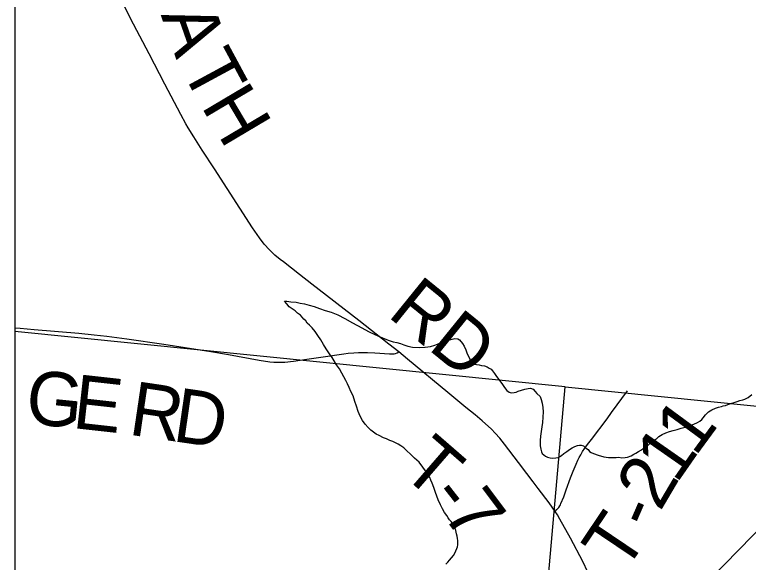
# Model space of a CAD drawing. Extents: x 0 to 34, y 0 to 22.
# Drawn here: x 22.516 to 23.289, y 17.774 to 18.35 of the extents above; entities that cross this region are included whole.
import ezdxf

# ---------------------------------------------------------------- set-up
doc = ezdxf.new("R2010")
doc.units = 0
for name, color, linetype in [('GM_X_County_Road', 7, 'Continuous'), ('GM_X_Minor_River', 7, 'Continuous'), ('GM_X_Section', 7, 'Continuous'), ('GM_X_State_Route', 7, 'Continuous'), ('GM_X_Township_Road', 7, 'Continuous'), ('GM_X_Township_Road_Text', 7, 'Continuous'), ('SH_Border', 7, 'Continuous'), ('SH_Data', 7, 'Continuous')]:
    doc.layers.add(name, color=color, linetype=linetype)

msp = doc.modelspace()

# ---------------------------------------------------------------- linework, layer by layer
at = {"layer": 'GM_X_County_Road'}
msp.add_lwpolyline([(22.51637, 18.01675), (22.51637, 17.0024), (23.00697, 16.95129), (23.09601, 17.95858)], close=True, dxfattribs=at)
at = {"layer": 'GM_X_Minor_River'}
for points in [[(22.97037, 17.77207), (22.9723, 17.77432), (22.97423, 17.77656), (22.97617, 17.77881), (22.97849, 17.78144), (22.97966, 17.7837), (22.98084, 17.78634), (22.98202, 17.7886), (22.98243, 17.7905), (22.98284, 17.79239), (22.98287, 17.79467), (22.98291, 17.79695), (22.98257, 17.79924), (22.98222, 17.80152), (22.98151, 17.8042), (22.9808, 17.80763), (22.97971, 17.81069), (22.97823, 17.813), (22.97713, 17.81529), (22.97602, 17.81721), (22.97415, 17.81876), (22.97267, 17.82107), (22.97118, 17.82337), (22.96895, 17.82645), (22.96674, 17.83029), (22.96453, 17.83451), (22.96234, 17.83987), (22.95942, 17.84752), (22.95761, 17.85287), (22.95578, 17.85746), (22.95431, 17.86053), (22.9536, 17.8632), (22.95249, 17.86512), (22.951, 17.86704), (22.94989, 17.86896), (22.94209, 17.87936), (22.93722, 17.88362), (22.93311, 17.88787), (22.92937, 17.89135), (22.926, 17.89445), (22.923, 17.89678), (22.91999, 17.89835), (22.91736, 17.89991), (22.91434, 17.9011), (22.91132, 17.90229), (22.90793, 17.90387), (22.90453, 17.90507), (22.90002, 17.90742), (22.897, 17.90899), (22.894, 17.91094), (22.89138, 17.91327), (22.88838, 17.91598), (22.8854, 17.91945), (22.88243, 17.9233), (22.88022, 17.9279), (22.87802, 17.93287), (22.87621, 17.93823), (22.87439, 17.9432), (22.87259, 17.94931), (22.87039, 17.95391), (22.86855, 17.95812), (22.86672, 17.96195), (22.86487, 17.9654), (22.86304, 17.96924), (22.86082, 17.97307), (22.85824, 17.97767), (22.85527, 17.98191), (22.85268, 17.98613), (22.85046, 17.98959), (22.84786, 17.99343), (22.84415, 17.99882), (22.84156, 18.00342), (22.8386, 18.00803), (22.83564, 18.01264), (22.83267, 18.01687), (22.82969, 18.02072), (22.8267, 18.02343), (22.82446, 18.02575), (22.82297, 18.02805), (22.82073, 18.02999), (22.81738, 18.03423), (22.81399, 18.03619), (22.81175, 18.0385), (22.8095, 18.04006), (22.80537, 18.04279), (22.80276, 18.04587), (22.80053, 18.04895), (22.80281, 18.04891)], [(22.80281, 18.04891), (22.80697, 18.04809), (22.81266, 18.04761), (22.81682, 18.04678), (22.82136, 18.04595), (22.82628, 18.04472), (22.83157, 18.04312), (22.83723, 18.04112), (22.84327, 18.03912), (22.84969, 18.03712), (22.85648, 18.03434), (22.86401, 18.03042), (22.87191, 18.0261), (22.8817, 18.02062), (22.88885, 18.01708), (22.89564, 18.01393), (22.90129, 18.01118), (22.90619, 18.0092), (22.91072, 18.0076), (22.91487, 18.00601), (22.91865, 18.00519), (22.92244, 18.00436), (22.92621, 18.00278), (22.93036, 18.00157), (22.93528, 18.00035), (22.94287, 18.00023), (22.94857, 18.00051), (22.95428, 18.00118), (22.95885, 18.00262), (22.96229, 18.00409), (22.96535, 18.00556), (22.96879, 18.00664), (22.97184, 18.00773), (22.97412, 18.00807), (22.97984, 18.0095), (22.98287, 18.00907), (22.98476, 18.00828), (22.98773, 18.00442), (22.98958, 18.00135), (22.99142, 17.99752), (22.99287, 17.99332), (22.99471, 17.98949), (22.99617, 17.98604), (22.99803, 17.98373), (23.00067, 17.98254), (23.00256, 17.98213), (23.00521, 17.98171), (23.00786, 17.98129), (23.01089, 17.98085), (23.01391, 17.97967), (23.01579, 17.97849), (23.01805, 17.97732), (23.01954, 17.97539), (23.02139, 17.9727), (23.02362, 17.96962), (23.02697, 17.965), (23.02994, 17.96116), (23.03217, 17.95808), (23.0344, 17.955), (23.03702, 17.95306), (23.03891, 17.95226), (23.04233, 17.95259), (23.04423, 17.95294), (23.04653, 17.95404), (23.04996, 17.95512), (23.0534, 17.95621), (23.05683, 17.95691), (23.05949, 17.95725), (23.06213, 17.95644), (23.06437, 17.95374), (23.06624, 17.95181), (23.0696, 17.94872), (23.07069, 17.94528), (23.07176, 17.94146), (23.07245, 17.93688), (23.07276, 17.93232), (23.0722, 17.9213), (23.07137, 17.91676), (23.07053, 17.91183), (23.07008, 17.90689), (23.06962, 17.90234), (23.06953, 17.89664), (23.07024, 17.89321), (23.07095, 17.89053), (23.07168, 17.88862), (23.07506, 17.8859), (23.07732, 17.88473), (23.07996, 17.88392), (23.083, 17.88387), (23.08604, 17.8842), (23.0887, 17.88454), (23.09215, 17.88638), (23.09446, 17.88862), (23.09753, 17.89085), (23.1006, 17.89271), (23.10329, 17.89456), (23.10597, 17.89604), (23.10902, 17.89713), (23.11093, 17.89747), (23.11282, 17.89744), (23.11509, 17.89665)], [(23.11509, 17.89665), (23.11733, 17.89471), (23.11996, 17.89277), (23.12145, 17.89084), (23.12333, 17.88967), (23.12559, 17.88849), (23.1305, 17.88689), (23.13654, 17.88527), (23.14147, 17.88443), (23.14412, 17.88438), (23.1464, 17.88435), (23.14944, 17.8843), (23.15248, 17.88462), (23.15551, 17.8842), (23.15893, 17.88452), (23.16159, 17.88486), (23.16541, 17.88631), (23.16809, 17.88779), (23.17039, 17.88889), (23.17308, 17.89075), (23.17614, 17.8926), (23.1796, 17.8952), (23.18304, 17.89704), (23.18574, 17.89966), (23.18882, 17.90227), (23.19189, 17.90412), (23.19458, 17.90636), (23.19803, 17.90858), (23.20186, 17.91042), (23.20568, 17.91188), (23.20949, 17.91295), (23.21368, 17.91402), (23.21788, 17.9151), (23.22359, 17.91652), (23.22741, 17.91798), (23.23123, 17.91944), (23.23506, 17.92127), (23.23774, 17.92275), (23.23966, 17.92424), (23.24121, 17.92611), (23.24354, 17.92912), (23.24663, 17.93249), (23.25046, 17.9347), (23.25428, 17.93616), (23.25733, 17.93725), (23.26038, 17.93796), (23.26229, 17.93869), (23.26457, 17.93903), (23.26725, 17.94013), (23.27679, 17.94339), (23.27984, 17.94448), (23.28289, 17.94519), (23.28518, 17.94591), (23.28862, 17.94738), (23.29247, 17.95073)]]:
    msp.add_lwpolyline(points, dxfattribs=at)
at = {"layer": 'GM_X_Section'}
msp.add_lwpolyline([(24.0891, 17.85881), (23.98418, 16.85292), (23.00697, 16.95129), (23.09601, 17.95858)], close=True, dxfattribs=at)
at = {"layer": 'GM_X_State_Route'}
msp.add_lwpolyline([(23.24886, 17.75663), (23.3079, 17.8171)], dxfattribs=at)
at = {"layer": 'GM_X_Township_Road'}
for points in [[(22.79922, 18.09016), (22.79599, 18.09269), (22.79041, 18.09729), (22.78447, 18.1028), (22.77898, 18.10883), (22.77403, 18.11531), (22.7667, 18.12604), (22.72669, 18.18796), (22.71371, 18.20778), (22.70496, 18.22167), (22.6991, 18.23095), (22.6966, 18.23521), (22.6912, 18.245), (22.67457, 18.27696), (22.65786, 18.30886), (22.63825, 18.34628), (22.62637, 18.37056)], [(22.92071, 17.99537), (22.91028, 18.00373), (22.87873, 18.02843), (22.82934, 18.06673), (22.81618, 18.07692), (22.79922, 18.09016)], [(22.51637, 18.02085), (22.52225, 18.02035), (22.53707, 18.01908), (22.58403, 18.01522), (22.59998, 18.01358), (22.61353, 18.01193), (22.63442, 18.00916), (22.67354, 18.0037), (22.72296, 17.99585), (22.74142, 17.9926), (22.77393, 17.9866), (22.78505, 17.9851), (22.78908, 17.98475), (22.79316, 17.98463), (22.7965, 17.98461), (22.80066, 17.98479), (22.80997, 17.98574), (22.82409, 17.98788), (22.84127, 17.99029), (22.86274, 17.99359), (22.86742, 17.99408), (22.87343, 17.99457), (22.87831, 17.99486), (22.8834, 17.99493), (22.88792, 17.99486), (22.8956, 17.9944), (22.91106, 17.99336), (22.91436, 17.99344), (22.91585, 17.99359), (22.9172, 17.99394), (22.91903, 17.99451), (22.92071, 17.99537)], [(23.08532, 17.82774), (23.07902, 17.83661), (23.06738, 17.8519), (23.06208, 17.8588), (23.05538, 17.86773), (23.04681, 17.87915), (23.03216, 17.89842), (23.0271, 17.90466), (23.02215, 17.91014), (23.01824, 17.91408), (23.00864, 17.92282), (23.00104, 17.92918), (22.99143, 17.93704), (22.97233, 17.95272), (22.93002, 17.98792), (22.92071, 17.99537)], [(23.08532, 17.82774), (23.08728, 17.82977), (23.08906, 17.83186), (23.09016, 17.83345), (23.0909, 17.83462), (23.09144, 17.83596), (23.09434, 17.84297), (23.09702, 17.85046), (23.1015, 17.86297), (23.10439, 17.87018), (23.10746, 17.87748), (23.10926, 17.88148), (23.11069, 17.88439), (23.11228, 17.88736), (23.11422, 17.8906), (23.11668, 17.89413), (23.11945, 17.898), (23.12353, 17.90341), (23.14, 17.92523), (23.14481, 17.93158), (23.16135, 17.95439)], [(23.14604, 17.66455), (23.14541, 17.66593), (23.14437, 17.66893), (23.14367, 17.67141), (23.14292, 17.67434), (23.13891, 17.69002), (23.13415, 17.71125), (23.12947, 17.73247), (23.12731, 17.74114), (23.1258, 17.74688), (23.12442, 17.75142), (23.12297, 17.75568), (23.12163, 17.75935), (23.11978, 17.76371), (23.11449, 17.77489), (23.10163, 17.79967), (23.09034, 17.81965), (23.08774, 17.82397), (23.08532, 17.82774)]]:
    msp.add_lwpolyline(points, dxfattribs=at)
at = {"layer": 'SH_Border'}
msp.add_lwpolyline([(22.51637, 19.03183), (22.51637, 14.97433)], dxfattribs=at)
at = {"layer": 'SH_Data'}
msp.add_line((22.51637, 20.26181), (22.51637, 13.46181), dxfattribs=at)
msp.add_lwpolyline([(22.51637, 19.03183), (22.51637, 13.46181)], dxfattribs=at)

# ---------------------------------------------------------------- texts
at = {"layer": 'GM_X_Township_Road_Text'}
for s, height, rotation, p in [('A', 0.05682, 289.36735, (22.67001, 18.34995)), ('T', 0.05682, 298.37755, (22.69053, 18.29386)), ('H', 0.05682, 300.67011, (22.71196, 18.25431)), ('RD', 0.056818, 320.95297, (22.90766, 18.0336)), ('G', 0.05682, 354.3445, (22.52653, 17.92047)), ('E', 0.05682, 353.65295, (22.57611, 17.91556)), ('R', 0.05682, 351.58233, (22.63516, 17.90864)), ('D', 0.05682, 351.73012, (22.68148, 17.90178)), ('1', 0.05682, 53.71399, (23.23268, 17.88435)), ('T', 0.05682, 319.0473, (22.92124, 17.86864)), ('1', 0.05682, 55.12564, (23.21289, 17.85593)), ('2', 0.05682, 59.48023, (23.19573, 17.82674)), ('-', 0.05682, 308.04237, (22.95136, 17.84287)), ('7', 0.05682, 306.92194, (22.96556, 17.82472)), ('-', 0.05682, 66.50807, (23.18726, 17.80698)), ('T', 0.05682, 56.03952, (23.15809, 17.76182))]:
    msp.add_text(s, height=height, rotation=rotation, dxfattribs=at).set_placement(p)

doc.saveas('drawing.dxf')
